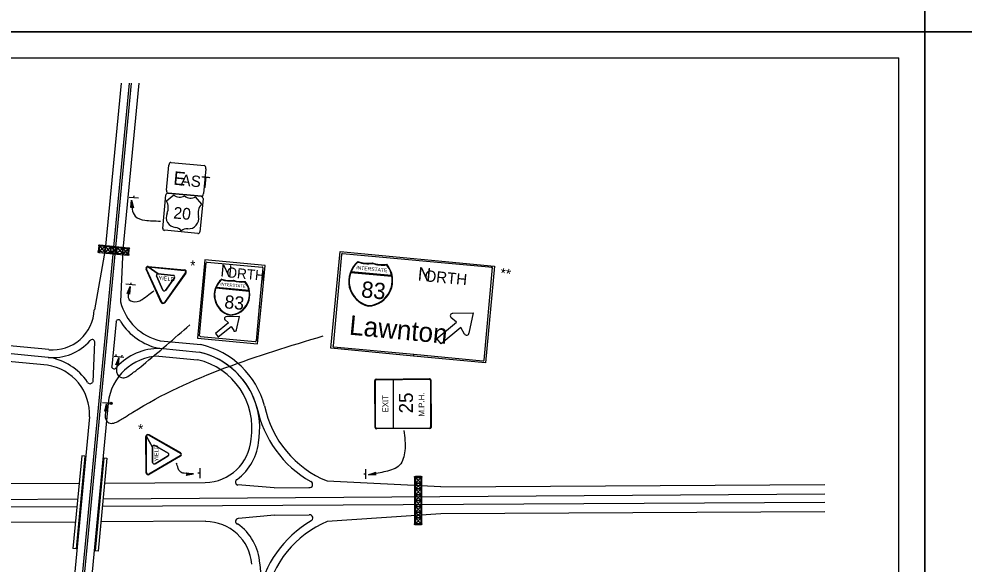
# Model space of a CAD drawing. Extents: x 644898 to 648326, y 298294 to 300670.
# Drawn here: x 646898 to 647444, y 299769 to 300084 of the extents above; entities that cross this region are included whole.
import ezdxf

# ---------------------------------------------------------------- set-up
doc = ezdxf.new("R2010")
doc.units = 0
for name, color, linetype in [('1', 7, 'Continuous'), ('2', 7, 'Continuous'), ('XCS-GRID-MIN', 7, 'Continuous')]:
    doc.layers.add(name, color=color, linetype=linetype)

msp = doc.modelspace()

# ---------------------------------------------------------------- linework, layer by layer
at = {"layer": '1'}
for p in [(646620.32, 300061.49), (647406.32, 299497.49)]:
    msp.add_line(p, (647406.32, 300061.49), dxfattribs=at)
at = {"layer": '2'}
for p, q in [((646961.82, 300046.87), (646916.95, 299575.99)), ((646962.95, 300046.87), (646918.07, 299575.99)), ((646957.32, 300046.87), (646948.07, 299950.99)), ((646967.45, 300046.87), (646958.2, 299950.99)), ((646983.45, 299985.24), (646984.82, 299999.49)), ((646986.07, 300001.12), (647005.32, 299999.37)), ((647006.2, 299997.49), (647004.82, 299983.24)), ((646994.82, 299991.37), (646994.82, 299991.37)), ((646967.32, 299980.49), (646961.82, 299980.99)), ((646964.57, 299980.87), (646964.7, 299981.87)), ((646981.32, 299963.12), (646983.07, 299982.37)), ((646983.45, 299978.99), (646987.7, 299982.49)), ((647003.57, 299981.62), (646984.32, 299983.37)), ((646984.32, 299983.37), (647003.57, 299981.62)), ((647000.07, 299981.24), (647003.7, 299976.99)), ((647004.57, 299980.37), (647002.7, 299960.99)), ((646992.95, 299971.74), (646992.95, 299971.74)), ((647002.07, 299968.12), (647002.07, 299968.12)), ((647001.57, 299960.12), (646982.32, 299961.99)), ((646988.57, 299963.62), (646988.57, 299963.62)), ((646995.7, 299962.87), (646995.7, 299962.87)), ((646961.57, 299951.74), (646944.95, 299953.49)), ((646948.07, 299950.99), (646941.82, 299916.12)), ((646944.32, 299952.99), (646944.07, 299949.74)), ((646944.82, 299952.99), (646944.45, 299949.74)), ((646944.45, 299949.74), (646948.07, 299952.74)), ((646944.45, 299949.12), (646961.2, 299947.62)), ((646944.82, 299952.99), (646947.82, 299949.37)), ((646947.82, 299949.37), (646951.45, 299952.37)), ((646948.07, 299952.74), (646951.2, 299948.99)), ((646948.07, 299950.99), (646948.07, 299950.99)), ((646951.2, 299948.99), (646954.95, 299952.12)), ((646951.45, 299952.37), (646954.45, 299948.62)), ((646953.07, 299950.49), (646953.07, 299950.49)), ((646953.07, 299950.49), (646953.07, 299950.49)), ((646954.45, 299948.62), (646958.2, 299951.62)), ((646954.95, 299952.12), (646957.95, 299948.37)), ((646958.2, 299950.99), (646956.95, 299920.74)), ((646957.95, 299948.37), (646961.57, 299951.37)), ((646958.2, 299951.62), (646961.2, 299947.99)), ((646958.2, 299950.99), (646958.2, 299950.99)), ((646961.2, 299947.99), (646961.57, 299951.37)), ((646961.7, 299947.99), (646961.95, 299951.37)), ((647078.36, 299893.95), (647083.73, 299949.71)), ((647084.61, 299948.08), (647079.61, 299895.33)), ((647083.73, 299949.7), (647172.86, 299941.2)), ((647005.68, 299945.03), (647001.43, 299899.78)), ((647002.56, 299901.03), (647006.43, 299943.28)), ((647040.44, 299941.76), (647005.68, 299945.03)), ((647006.93, 299943.65), (647038.68, 299940.78)), ((647094.11, 299943.58), (647094.11, 299943.58)), ((647102.36, 299942.83), (647102.36, 299942.83)), ((646980.45, 299920.37), (646971.7, 299939.49)), ((646980.7, 299920.49), (646971.95, 299939.62)), ((646980.7, 299920.49), (646971.95, 299939.62)), ((646972.82, 299940.87), (646978.57, 299936.87)), ((646972.95, 299941.12), (646993.82, 299939.12)), ((646972.95, 299940.87), (646993.7, 299938.87)), ((646978.57, 299936.87), (646972.95, 299940.87)), ((646978.57, 299936.87), (646972.95, 299940.87)), ((646972.95, 299940.87), (646993.7, 299938.87)), ((646978.57, 299936.87), (646987.45, 299935.99)), ((646987.45, 299935.99), (646978.57, 299936.87)), ((646994.32, 299937.49), (646982.2, 299920.37)), ((646994.32, 299937.49), (646982.2, 299920.37)), ((646994.7, 299937.24), (646982.45, 299920.24)), ((647039.05, 299940.28), (647037, 299917.73)), ((647038.1, 299917.62), (647040.44, 299941.76)), ((647089.98, 299937.7), (647113.48, 299935.45)), ((647113.48, 299935.83), (647090.11, 299938.08)), ((647110.48, 299942.08), (647110.48, 299942.08)), ((647166.86, 299887.08), (647171.67, 299940.54)), ((647172.86, 299941.2), (647167.61, 299885.45)), ((646962.82, 299930.74), (646962.95, 299931.74)), ((646981.32, 299927.49), (646977.7, 299935.62)), ((646977.7, 299935.62), (646981.32, 299927.49)), ((646982.7, 299932.87), (646982.7, 299932.87)), ((646988.07, 299934.62), (646982.95, 299927.24)), ((646982.95, 299927.24), (646988.07, 299934.62)), ((646965.57, 299930.37), (646959.95, 299930.99)), ((647012, 299928.8), (647031.13, 299926.92)), ((647031.13, 299927.17), (647012.13, 299929.05)), ((647036.98, 299917.73), (647035.19, 299898.13)), ((647036.05, 299896.53), (647038.1, 299917.62)), ((647038.1, 299917.62), (647036.98, 299917.73)), ((647037, 299917.73), (647038.1, 299917.62)), ((646954.32, 299909.37), (646951.82, 299883.37)), ((646954.32, 299909.37), (646954.32, 299909.37)), ((647017.13, 299910.42), (647019.25, 299908.55)), ((647017.13, 299910.42), (647019.25, 299908.55)), ((647025.63, 299912.17), (647017.75, 299912.05)), ((647025.63, 299912.17), (647017.75, 299912.05)), ((647023.88, 299904.55), (647025.63, 299912.17)), ((647023.88, 299904.55), (647025.63, 299912.17)), ((647150.98, 299908.95), (647147.73, 299911.58)), ((647148.73, 299914.08), (647160.61, 299914.33)), ((647160.61, 299914.33), (647158.11, 299902.58)), ((647019.25, 299908.55), (647011.75, 299902.42)), ((647019.25, 299908.55), (647011.75, 299902.42)), ((647013.38, 299900.42), (647020.88, 299906.55)), ((647013.38, 299900.42), (647020.88, 299906.55)), ((647020.88, 299906.55), (647022.25, 299904.17)), ((647020.88, 299906.55), (647022.25, 299904.17)), ((647024, 299904.55), (647023.88, 299904.55)), ((647024, 299904.55), (647023.88, 299904.55)), ((647139.61, 299899.58), (647150.98, 299908.95)), ((647153.48, 299905.83), (647142.11, 299896.45)), ((647155.61, 299902.08), (647153.48, 299905.83)), ((647001.43, 299899.78), (647036.05, 299896.53)), ((647034.68, 299897.65), (647003.06, 299900.53)), ((647011.75, 299902.42), (647013.38, 299900.42)), ((647011.75, 299902.42), (647013.38, 299900.42)), ((647142.11, 299896.45), (647139.61, 299899.58)), ((646915.57, 299893.12), (646886.41, 299895.9)), ((646941.95, 299897.62), (646940.82, 299874.37)), ((646979.56, 299893.86), (647002.32, 299891.62)), ((646979.95, 299898.24), (647003.32, 299895.99)), ((647126.15, 299889.4), (647078.36, 299893.95)), ((647079.98, 299894.7), (647126.25, 299890.41)), ((646915.07, 299888.62), (646885.65, 299891.41)), ((646915.07, 299888.62), (646915.07, 299888.62)), ((646958.82, 299888.62), (646953.2, 299889.12)), ((646954.32, 299889.12), (646954.45, 299890.24)), ((646957.7, 299888.74), (646957.82, 299889.87)), ((646979.07, 299889.37), (647001.32, 299887.24)), ((647126.15, 299889.4), (647126.25, 299890.41)), ((647126.25, 299890.41), (647126.15, 299889.4)), ((647167.61, 299885.45), (647126.15, 299889.4)), ((647126.25, 299890.41), (647166.23, 299886.7)), ((646914.7, 299884.12), (646885.14, 299886.91)), ((646951.82, 299883.37), (646951.82, 299883.37)), ((647103.95, 299848.12), (647103.82, 299875.37)), ((647104.2, 299848.24), (647104.07, 299875.12)), ((647104.45, 299876.12), (647135.45, 299876.37)), ((647104.57, 299875.74), (647135.2, 299875.99)), ((647114.57, 299847.74), (647114.45, 299875.87)), ((647135.82, 299875.37), (647135.95, 299848.49)), ((647136.07, 299875.62), (647136.32, 299848.24)), ((646949.82, 299862.24), (646939.45, 299754.37)), ((646951.95, 299861.99), (646946.45, 299862.49)), ((646949.82, 299862.24), (646949.82, 299862.24)), ((646938.95, 299854.24), (646928.7, 299745.49)), ((646938.57, 299849.74), (646938.57, 299849.74)), ((646948.95, 299853.12), (646948.95, 299853.12)), ((646973.33, 299844.03), (646991.58, 299833.65)), ((647135.7, 299847.62), (647104.57, 299847.37)), ((647135.45, 299847.87), (647104.82, 299847.62)), ((646971.71, 299821.9), (646971.58, 299843.03)), ((646971.96, 299821.9), (646971.96, 299843.03)), ((646975.33, 299836.9), (646971.96, 299843.03)), ((646975.33, 299836.9), (646971.96, 299843.03)), ((646971.96, 299821.9), (646971.96, 299843.03)), ((646971.96, 299843.03), (646975.33, 299836.9)), ((646973.21, 299843.65), (646991.33, 299833.4)), ((646973.21, 299843.65), (646991.33, 299833.4)), ((646975.46, 299828.03), (646975.33, 299836.9)), ((646975.33, 299836.9), (646975.46, 299828.03)), ((646976.71, 299837.78), (646984.46, 299833.28)), ((646984.46, 299833.28), (646976.71, 299837.78)), ((646934.57, 299831.87), (646929.45, 299778.24)), ((646936.2, 299831.62), (646931.2, 299778.12)), ((646936.2, 299831.62), (646934.57, 299831.87)), ((646947.32, 299830.62), (646942.32, 299776.99)), ((646949.07, 299830.49), (646943.95, 299776.87)), ((646947.32, 299830.62), (646949.07, 299830.49)), ((646991.33, 299831.78), (646973.33, 299821.15)), ((646991.33, 299831.78), (646973.33, 299821.15)), ((646991.58, 299831.65), (646973.46, 299821.03)), ((646984.46, 299831.78), (646976.83, 299827.28)), ((646976.83, 299827.28), (646984.46, 299831.78)), ((647002.7, 299824.62), (647002.7, 299818.99)), ((647098.32, 299824.12), (647098.32, 299818.49)), ((647002.7, 299821.74), (647001.57, 299821.74)), ((647141.82, 299813.87), (647076.2, 299817.24)), ((647098.32, 299821.24), (647097.32, 299821.24)), ((647127.2, 299819.37), (647130.45, 299815.99)), ((647130.45, 299819.37), (647127.2, 299815.99)), ((646874.82, 299815.74), (646933.07, 299815.99)), ((646947.57, 299816.12), (647005.82, 299816.49)), ((647005.82, 299816.49), (647005.82, 299816.49)), ((647045.7, 299813.37), (647024.7, 299814.99)), ((647045.7, 299813.37), (647065.7, 299813.49)), ((647127.2, 299815.99), (647130.45, 299812.74)), ((647130.45, 299815.99), (647127.2, 299812.74)), ((647127.2, 299812.74), (647130.45, 299809.37)), ((647130.45, 299812.74), (647127.2, 299809.37)), ((647141.82, 299813.87), (647363.57, 299815.27)), ((646932.2, 299806.74), (646632.96, 299804.85)), ((647363.57, 299809.66), (646946.82, 299806.87)), ((647127.2, 299809.37), (647130.45, 299805.99)), ((647130.45, 299809.37), (647127.2, 299805.99)), ((647127.2, 299805.99), (647130.45, 299802.62)), ((647130.45, 299805.99), (647127.2, 299802.62)), ((646633.01, 299800.83), (646931.82, 299802.62)), ((646946.32, 299802.74), (647363.57, 299805.13)), ((647127.2, 299802.62), (647130.45, 299799.24)), ((647130.45, 299802.62), (647127.2, 299799.24)), ((647045.82, 299797.49), (647024.95, 299795.62)), ((647045.82, 299797.49), (647065.82, 299797.74)), ((647141.95, 299798.24), (647076.32, 299793.99)), ((647127.2, 299799.24), (647130.45, 299795.99)), ((647130.45, 299799.24), (647127.2, 299795.99)), ((647127.2, 299795.99), (647130.45, 299792.49)), ((647130.45, 299795.99), (647127.2, 299792.49)), ((647130.45, 299792.49), (647130.45, 299795.99)), ((647363.57, 299799.51), (647141.95, 299798.24)), ((646930.95, 299793.62), (646868.32, 299793.24)), ((647006.07, 299794.12), (646945.57, 299793.74)), ((647003.7, 299794.12), (647003.7, 299794.12)), ((646931.2, 299778.12), (646929.45, 299778.24)), ((646943.95, 299776.87), (646942.32, 299776.99))]:
    msp.add_line(p, q, dxfattribs=at)
for points in [[(646963.03, 299975.24), (646963.3, 299975.34), (646963.33, 299979.41), (646963.03, 299975.24), (646962.86, 299975.06), (646963.33, 299979.41), (646963.83, 299975.36), (646964.09, 299975.28), (646963.33, 299979.41), (646964.37, 299975.03), (646964.09, 299975.28)], [(647171.67, 299940.54), (647085.11, 299948.45)], [(646960.95, 299925.65), (646961.22, 299925.67), (646962.38, 299929.57), (646960.95, 299925.65), (646960.73, 299925.52), (646962.38, 299929.57), (646961.74, 299925.54), (646961.97, 299925.39), (646962.38, 299929.57), (646962.17, 299925.07), (646961.97, 299925.39)], [(646954.41, 299884.51), (646954.69, 299884.53), (646955.84, 299888.43), (646954.41, 299884.51), (646954.2, 299884.38), (646955.84, 299888.43), (646955.2, 299884.4), (646955.44, 299884.25), (646955.84, 299888.43), (646955.63, 299883.93), (646955.44, 299884.25)], [(646948.11, 299857.67), (646948.38, 299857.75), (646948.73, 299861.81), (646948.11, 299857.67), (646947.93, 299857.51), (646948.73, 299861.81), (646948.91, 299857.73), (646949.17, 299857.63), (646948.73, 299861.81), (646949.43, 299857.35), (646949.17, 299857.63)], [(647104.28, 299821.08), (647104.03, 299821.33), (647100.16, 299820.83), (647104.28, 299821.08), (647104.53, 299820.95), (647100.16, 299820.83), (647104.03, 299821.7), (647104.03, 299821.95), (647100.16, 299820.83), (647104.28, 299822.33), (647104.03, 299821.95)], [(646994.97, 299821.7), (646995.09, 299821.45), (646999.09, 299821.33), (646994.97, 299821.7), (646994.84, 299821.95), (646999.09, 299821.33), (646995.09, 299821.08), (646994.97, 299820.7), (646999.09, 299821.33), (646994.84, 299820.45), (646994.97, 299820.7)], [(647126.7, 299819.37), (647126.7, 299792.49)], [(647130.45, 299819.87), (647127.2, 299819.87)], [(647127.2, 299792.49), (647130.45, 299792.49), (647130.45, 299819.37), (647127.2, 299819.37), (647127.2, 299792.49)], [(647130.95, 299792.49), (647130.95, 299819.37)], [(647127.2, 299792.12), (647130.45, 299792.12)]]:
    msp.add_lwpolyline(points, dxfattribs=at)
for points in [[(646947.82, 299949.37), (646944.45, 299949.74), (646944.82, 299952.99), (646948.07, 299952.74)], [(646951.2, 299948.99), (646947.82, 299949.37), (646948.07, 299952.74), (646951.45, 299952.37)], [(646954.45, 299948.62), (646951.2, 299948.99), (646951.45, 299952.37), (646954.95, 299952.12)], [(646957.95, 299948.37), (646954.45, 299948.62), (646954.95, 299952.12), (646958.2, 299951.62)], [(646961.2, 299947.99), (646957.95, 299948.37), (646958.2, 299951.62), (646961.57, 299951.37)], [(647127.2, 299815.99), (647127.2, 299819.37), (647130.45, 299819.37), (647130.45, 299815.99)], [(647127.2, 299812.74), (647127.2, 299815.99), (647130.45, 299815.99), (647130.45, 299812.74)], [(647127.2, 299809.37), (647127.2, 299812.74), (647130.45, 299812.74), (647130.45, 299809.37)], [(647127.2, 299805.99), (647127.2, 299809.37), (647130.45, 299809.37), (647130.45, 299805.99)], [(647127.2, 299802.62), (647127.2, 299805.99), (647130.45, 299805.99), (647130.45, 299802.62)], [(647127.2, 299799.24), (647127.2, 299802.62), (647130.45, 299802.62), (647130.45, 299799.24)], [(647127.2, 299795.99), (647127.2, 299799.24), (647130.45, 299799.24), (647130.45, 299795.99)], [(647127.2, 299792.49), (647127.2, 299795.99), (647130.45, 299795.99), (647130.45, 299792.49)]]:
    msp.add_lwpolyline(points, close=True, dxfattribs=at)
for centre, radius in [((646944.61, 299953.22), 0.3), ((646944.25, 299949.46), 0.3), ((646961.4, 299947.83), 0.3), ((646961.76, 299951.59), 0.3), ((646951.33, 299862.06), 0.685), ((647126.96, 299819.65), 0.301), ((647130.74, 299819.65), 0.301), ((647126.96, 299792.35), 0.301), ((647130.74, 299792.35), 0.301)]:
    msp.add_circle(centre, radius, dxfattribs=at)
for centre, radius, start, end in [((646984.22, 299982.28), 1.07, 84.5662, 174.5662), ((646991.17, 299986.34), 5.23, 227.7022, 301.4303), ((646997.41, 299985.74), 5.23, 227.7022, 301.4303), ((647003.48, 299980.45), 1.07, 354.5662, 84.5662), ((646976.34, 299975.02), 8.13, 336.3952, 29.141), ((647009.84, 299971.83), 8.13, 139.9915, 192.7373), ((646989.11, 299969.4), 5.82, 156.0183, 264.5615), ((646996.24, 299968.72), 5.82, 264.571, 13.1142), ((646982.38, 299963.02), 1.07, 174.5662, 264.5662), ((646988.09, 299958.7), 4.93, 38.2937, 84.5662), ((646995.23, 299958.02), 4.93, 84.5662, 130.8388), ((647001.65, 299961.19), 1.07, 264.5662, 354.5662), ((647085.05, 299948), 0.528, 84.2894, 175.6013), ((647006.99, 299943.31), 0.42, 84.742, 174.8057), ((647103.43, 299932.58), 14.78, 129.5662, 256.4361), ((647103.43, 299932.58), 14.47, 130.2586, 157.7735), ((647099.74, 299959.96), 16.98, 250.3162, 278.8163), ((647099.74, 299959.96), 17.29, 250.9067, 278.5552), ((647099.27, 299932.97), 14.78, 272.6963, 39.5662), ((647108.06, 299959.17), 17.29, 250.5773, 278.2258), ((647108.06, 299959.17), 16.98, 250.3162, 278.8163), ((646972.78, 299940), 1.18, 84.5662, 204.5663), ((646972.78, 299940), 0.871, 84.5662, 204.5663), ((646972.78, 299940), 0.871, 84.5662, 204.5663), ((646978.46, 299935.96), 0.871, 84.5662, 204.5662), ((646978.46, 299935.96), 0.871, 84.5662, 204.5662), ((646993.68, 299938.02), 0.871, 324.5662, 84.5662), ((646993.68, 299938.02), 0.871, 324.5662, 84.5662), ((646993.68, 299938.02), 1.18, 324.5662, 84.5662), ((647038.73, 299940.35), 0.42, 354.0939, 85.0303), ((647103.43, 299932.58), 14.47, 159.0531, 256.4361), ((647099.27, 299932.97), 14.47, 11.359, 38.8739), ((647171.16, 299939.9), 0.528, 354.144, 84.5077), ((646987.35, 299935.12), 0.871, 324.5663, 84.5662), ((646987.35, 299935.12), 0.871, 324.5663, 84.5662), ((647022.97, 299924.56), 11.97, 129.5662, 256.4361), ((647022.97, 299924.56), 11.72, 130.2586, 157.7735), ((647019.98, 299946.74), 13.76, 250.3162, 278.8163), ((647019.98, 299946.74), 14.01, 250.9067, 278.5552), ((647019.6, 299924.88), 11.97, 272.6963, 39.5662), ((647026.72, 299946.1), 14.01, 250.5773, 278.2258), ((647026.72, 299946.1), 13.76, 250.3162, 278.8163), ((647019.6, 299924.88), 11.72, 11.359, 38.8739), ((647099.27, 299932.97), 14.47, 272.6964, 10.0794), ((646982.17, 299927.85), 0.871, 204.5663, 324.5662), ((646982.17, 299927.85), 0.871, 204.5663, 324.5662), ((647022.97, 299924.56), 11.72, 159.0531, 256.4361), ((647019.6, 299924.88), 11.72, 272.6964, 10.0794), ((646986.24, 299927.7), 30.1, 193.3923, 257.789), ((646981.51, 299920.91), 1.18, 204.5663, 324.5662), ((646981.51, 299920.91), 0.871, 204.5663, 324.5662), ((646981.51, 299920.91), 0.871, 204.5663, 324.5662), ((646917.73, 299917), 24.02, 264.6308, 357.9333), ((646955.65, 299908.9), 1.47, 7.1345, 160.9311), ((647017.79, 299911.08), 0.916, 89.4252, 230.0907), ((647017.79, 299911.08), 0.916, 89.4252, 230.0907), ((647148.75, 299912.65), 1.4, 89.4252, 230.0907), ((646986.23, 299927.7), 34.57, 212.5881, 257.7912), ((647023.04, 299904.65), 0.916, 207.8136, 351.7203), ((647023.04, 299904.65), 0.916, 207.8136, 351.7203), ((646940.48, 299897.39), 1.53, 9.3098, 140.8858), ((647003.12, 299901.07), 0.42, 175.1355, 263.8845), ((647156.76, 299902.85), 1.4, 207.8136, 351.7203), ((646917.73, 299917), 28.5, 264.6308, 319.1479), ((646979.73, 299859.28), 34.57, 90.2672, 136.5449), ((646992.54, 299847.94), 49.23, 14.982, 77.4127), ((647080.06, 299895.26), 0.528, 174.0939, 265.2364), ((646910.32, 299855.83), 33.15, 34.0358, 81.3457), ((646979.73, 299859.28), 30.09, 91.3419, 174.3352), ((646992.54, 299847.94), 44.75, 350.6257, 77.4127), ((646992.54, 299847.94), 44.75, 14.982, 77.4127), ((646910.32, 299855.83), 28.67, 356.9079, 81.3457), ((646953.23, 299883.51), 1.47, 188.202, 341.9985), ((646992.54, 299847.94), 40.27, 350.6257, 77.4127), ((647166.3, 299887.14), 0.528, 264.8056, 354.9575), ((646939.28, 299875.11), 1.67, 206.0643, 335.1102), ((647098.55, 299872.61), 59.66, 191.542, 247.9601), ((647098.55, 299872.61), 64.14, 191.542, 240.2801), ((646972.73, 299842.98), 1.18, 60.3746, 180.3747), ((646972.73, 299842.98), 0.871, 60.3746, 180.3747), ((646972.73, 299842.98), 0.871, 60.3746, 180.3747), ((647005.54, 299843.26), 26.8, 270.6921, 355.9731), ((647005.54, 299843.26), 31.28, 306.6668, 355.9731), ((646976.25, 299836.97), 0.871, 60.3747, 180.3747), ((646976.25, 299836.97), 0.871, 60.3747, 180.3747), ((646984.01, 299832.56), 0.871, 300.3747, 60.3746), ((646984.01, 299832.56), 0.871, 300.3747, 60.3746), ((646990.98, 299832.6), 0.871, 300.3747, 60.3746), ((646990.98, 299832.6), 0.871, 300.3747, 60.3746), ((646990.98, 299832.6), 1.18, 300.3747, 60.3746), ((646976.31, 299828.04), 0.871, 180.3746, 300.3746), ((646976.31, 299828.04), 0.871, 180.3747, 300.3746), ((646972.87, 299821.99), 1.18, 180.3747, 300.3747), ((646972.87, 299821.99), 0.871, 180.3746, 300.3747), ((646972.87, 299821.99), 0.871, 180.3746, 300.3747), ((647024.89, 299816.65), 1.69, 113.864, 263.9377), ((647066.04, 299815.25), 1.81, 261.3339, 66.4393), ((647025.04, 299793.96), 1.69, 96.8106, 246.8843), ((647066.16, 299795.9), 1.81, 294.3091, 99.4145), ((647006.04, 299767.1), 26.8, 4.7753, 90.0563), ((647006.04, 299767.1), 31.51, 4.7753, 54.0816), ((647099.43, 299738.97), 64.14, 120.4682, 169.2063), ((647099.43, 299738.97), 59.66, 112.7883, 169.2063), ((646990.11, 299762.94), 47.84, 263.7511, 8.5263)]:
    msp.add_arc(centre, radius, start, end, dxfattribs=at)
for centre, major_axis, ratio, start_param, end_param in [((646985.84, 299999.4), (-0.17, -1.78), 0.6, 3.141593, 4.712389), ((647005.11, 299997.57), (0.17, 1.78), 0.6, 4.712389, 6.283185), ((646984.49, 299985.14), (-0.17, -1.78), 0.6, 4.712389, 6.283185), ((647003.75, 299983.3), (0.17, 1.78), 0.6, 3.141593, 4.712389), ((647034.75, 299898.19), (-0.431, 0), 0.924248, 1.489344, 3.050933), ((647104.45, 299875.36), (0.005, -0.717), 0.9, 3.141593, 4.712389), ((647104.64, 299875.15), (0.004, -0.657), 0.9, 3.141593, 4.712389), ((647135.24, 299875.35), (-0.004, 0.657), 0.9, 4.712389, 6.283185), ((647135.42, 299875.56), (-0.005, 0.717), 0.9, 4.712389, 6.283185), ((647104.63, 299848.11), (0.005, -0.717), 0.9, 4.712389, 6.283185), ((647104.82, 299848.33), (0.004, -0.657), 0.9, 4.712389, 6.283185), ((647135.41, 299848.53), (-0.004, 0.657), 0.9, 3.141593, 4.712389), ((647135.6, 299848.32), (0.005, -0.717), 0.9, 0, 1.570796)]:
    msp.add_ellipse(centre, major_axis=major_axis, ratio=ratio, start_param=start_param, end_param=end_param, dxfattribs=at)
for points in [[(646963.32, 299979.24), (646963.57, 299974.25), (646965.39, 299970.13), (646970.96, 299967.8), (646975.2, 299967.49), (646979.95, 299967.24)], [(646962.15, 299928.48), (646961.24, 299924.54), (646961.97, 299921.94), (646966.45, 299920.82), (646969.41, 299922.06), (646973.32, 299924.91), (646976.2, 299927.12)], [(646955.43, 299886.49), (646955.07, 299884.99), (646955.1, 299878.77), (646957.52, 299876.93), (646960.27, 299877.29), (646963.24, 299879.11), (646965.69, 299880.92), (646969.9, 299884.31), (646996.95, 299907.37)], [(646948.6, 299860.26), (646948.51, 299858.66), (646948.54, 299852.44), (646950.96, 299850.6), (646953.72, 299850.96), (646956.79, 299852.59), (646959.5, 299854.2), (646964.05, 299857.03), (647073.97, 299901.07)], [(647120.56, 299846.5), (647121.11, 299834.7), (647118.08, 299826.46), (647110.03, 299822.74), (647101.41, 299821.05)], [(646999.09, 299821.33), (646993.6, 299821.81), (646991.12, 299822.9), (646989.24, 299827.41), (646989.28, 299827.02)]]:
    msp.add_spline(points, degree=3, dxfattribs=at)
at = {"layer": 'XCS-GRID-MIN'}
for points in [[(646580.32, 300670.49), (647421.32, 300670.49), (647421.32, 300076.49), (646580.32, 300076.49)], [(647421.32, 300670.49), (648262.32, 300670.49), (648262.32, 300076.49), (647421.32, 300076.49)], [(646580.32, 300076.49), (647421.32, 300076.49), (647421.32, 299482.49), (646580.32, 299482.49)], [(647421.32, 300076.49), (648262.32, 300076.49), (648262.32, 299482.49), (647421.32, 299482.49)]]:
    msp.add_lwpolyline(points, close=True, dxfattribs=at)

# ---------------------------------------------------------------- texts
at = {"layer": '2'}
for s, height, rotation, p in [('E', 7.75, 354.5817, (646987.2, 299988.37)), ('AST', 6.5, 354.5683, (646991.44, 299987.87)), ('20', 6.75, 354.5663, (646987.2, 299968.87)), ('N', 6.97, 354.5817, (647014.38, 299935.42)), ('ORTH', 5.85, 354.5683, (647017.88, 299934.92)), ('INTERSTATE', 2.089, 354.5668, (647092.98, 299939.45)), ('N', 7.75, 354.5817, (647128.34, 299933.08)), ('ORTH', 6.5, 354.5683, (647132.23, 299932.58)), ('**', 5.853, 351.9371, (647175.88, 299934.59)), ('YIELD', 2.383, 354.5663, (646978.7, 299933.37)), ('INTERSTATE', 1.693, 354.5666, (647014.5, 299930.17)), ('83', 9.406, 354.5658, (647095.61, 299923.33)), ('83', 7.618, 354.5657, (647016.63, 299917.04)), ('Lawnton', 11.25, 354.5683, (647088.61, 299901.81)), ('EXIT', 3.387, 90.3745, (647111.57, 299856.87)), ('25', 8.061, 90.3746, (647125.82, 299856.37)), ('M.P.H.', 3.387, 90.3746, (647132.45, 299854.49)), ('35', 0.0217, 90, (647115.82, 299857.62)), ('YIELD', 2.383, 90.3738, (646978.83, 299828.53))]:
    msp.add_text(s, height=height, rotation=rotation, dxfattribs=at).set_placement(p)
for p in [(646997.12, 299938.73), (646967.04, 299844.32)]:
    msp.add_text('*', height=5.85, dxfattribs=at).set_placement(p)

doc.saveas('drawing.dxf')
